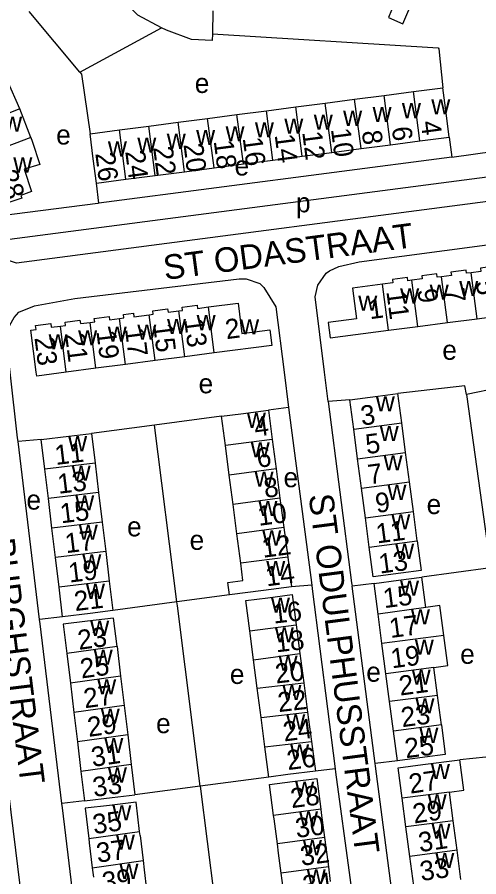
# Model space of a CAD drawing. Extents: x 161141 to 163125, y 381621 to 383200.
# Drawn here: x 162353 to 162447, y 382330.5 to 382505.7 of the extents above; entities that cross this region are included whole.
import ezdxf

# ---------------------------------------------------------------- set-up
doc = ezdxf.new("R2010")
doc.units = 0
for name, color, linetype in [('BLT_Basislijn', 7, 'Continuous'), ('BLT_Bebouwing', 7, 'Continuous'), ('BLT_Centroide', 7, 'Continuous'), ('BLT_Huisnummer', 7, 'Continuous'), ('BLT_Huisnummer_ tussenligend', 7, 'Continuous'), ('BLT_Onderverdeling_panden', 7, 'Continuous'), ('BLT_Straatnaam', 7, 'Continuous')]:
    doc.layers.add(name, color=color, linetype=linetype)

msp = doc.modelspace()

# ---------------------------------------------------------------- linework, layer by layer
at = {"layer": 'BLT_Basislijn'}
for p, q in [((162365.73, 382494.5), (162355.42, 382506.85)), ((162365.73, 382494.5), (162382.4, 382503.53)), ((162440.99, 382481.23), (162441.54, 382477.15)), ((162441.54, 382477.15), (162369.65, 382467.77)), ((162369.65, 382467.77), (162369.15, 382471.85)), ((162457.66, 382431.55), (162444.54, 382428.75)), ((162420.77, 382427.7), (162416.35, 382427.33)), ((162408.28, 382426.15), (162404.17, 382425.59)), ((162408.28, 382426.15), (162412.99, 382389.92)), ((162394.61, 382424.34), (162381, 382422.53)), ((162381, 382422.53), (162368.13, 382420.83)), ((162385.53, 382386.49), (162381, 382422.53)), ((162357.9, 382419.6), (162353.18, 382419.2)), ((162357.58, 382382.92), (162353.18, 382419.2)), ((162449.39, 382393.43), (162435.44, 382391.55)), ((162425.69, 382390.28), (162421.2, 382389.74)), ((162412.99, 382389.92), (162408.89, 382389.59)), ((162425.94, 382353.56), (162421.2, 382389.74)), ((162396.24, 382387.93), (162385.53, 382386.49)), ((162385.53, 382386.49), (162372.48, 382384.73)), ((162362.24, 382383.49), (162357.58, 382382.92)), ((162454.46, 382355.5), (162443.13, 382354.34)), ((162430.43, 382354.13), (162425.94, 382353.56)), ((162417.76, 382352.5), (162413.73, 382352.04)), ((162404.26, 382350.8), (162390.29, 382348.97)), ((162390.29, 382348.97), (162376.98, 382347.21)), ((162390.29, 382348.97), (162395.73, 382305.37)), ((162366.72, 382345.98), (162362.13, 382345.43))]:
    msp.add_line(p, q, dxfattribs=at)
for points in [[(162392.76, 382502.28), (162438.72, 382499.42), (162438.88, 382499.22), (162439.68, 382491.28)], [(162365.73, 382494.5), (162366.1, 382494.08), (162367.84, 382481.91)], [(162441.54, 382477.15), (162459.41, 382479.67), (162461.38, 382480.41), (162463.11, 382482.31), (162463.61, 382484.98)], [(162464.97, 382470.2), (162464.33, 382475.08), (162348.22, 382459.93)], [(162464.97, 382470.2), (162352.84, 382455.52), (162350.45, 382456.39), (162349.43, 382457.35), (162348.52, 382458.94), (162348.22, 382459.93)], [(162369.65, 382467.77), (162369.4, 382467.73), (162346.52, 382464.77)], [(162416.35, 382427.33), (162415.59, 382433.33), (162413.66, 382448.66), (162414.21, 382451.07), (162415.94, 382453.49), (162416.63, 382454), (162418.54, 382454.83), (162422.63, 382455.82), (162466.12, 382461.57)], [(162353.18, 382419.2), (162353.09, 382419.93), (162351.56, 382433.33), (162350.83, 382439.71), (162351.54, 382442.89), (162352.39, 382444.47), (162353.32, 382445.55), (162356.51, 382446.83), (162364.73, 382448.34), (162398.2, 382452.33), (162399.64, 382452.33), (162402.4, 382451.37), (162403.22, 382450.61), (162405.69, 382446.67), (162407.37, 382433.33), (162408.28, 382426.15)], [(162444.54, 382428.75), (162444.2, 382430.57), (162430.54, 382428.98)], [(162416.35, 382427.33), (162421.12, 382390.37), (162421.2, 382389.74)], [(162444.54, 382428.75), (162449.3, 382394.04), (162449.39, 382393.43)], [(162355.54, 382276.25), (162359.22, 382282.82), (162341.87, 382423.88)], [(162412.99, 382389.92), (162413.1, 382389.14), (162417.76, 382352.5)], [(162390.29, 382348.97), (162385.63, 382385.69), (162385.53, 382386.49)], [(162362.13, 382345.43), (162357.68, 382382.05), (162357.58, 382382.92)], [(162431.6, 382310.12), (162431.56, 382310.42), (162426.01, 382353.01), (162425.94, 382353.56)], [(162417.76, 382352.5), (162417.85, 382351.78), (162423.65, 382308.91)], [(162367.4, 382301.68), (162362.24, 382344.51), (162362.13, 382345.43)]]:
    msp.add_lwpolyline(points, dxfattribs=at)
at = {"layer": 'BLT_Bebouwing'}
for p, q in [((162392.85, 382506.99), (162392.76, 382502.28)), ((162353.52, 382486.97), (162351, 382492.7)), ((162427.71, 382489.72), (162433.7, 382490.5)), ((162433.7, 382490.5), (162439.68, 382491.28)), ((162415.74, 382488.16), (162421.72, 382488.94)), ((162421.72, 382488.94), (162427.71, 382489.72)), ((162355.75, 382481.16), (162353.52, 382486.97)), ((162403.76, 382486.6), (162409.75, 382487.38)), ((162409.75, 382487.38), (162415.74, 382488.16)), ((162385.8, 382484.25), (162391.79, 382485.03)), ((162391.79, 382485.03), (162397.77, 382485.81)), ((162397.77, 382485.81), (162403.76, 382486.6)), ((162373.83, 382482.69), (162379.81, 382483.47)), ((162379.81, 382483.47), (162385.8, 382484.25)), ((162367.84, 382481.91), (162373.83, 382482.69)), ((162423.04, 382478.88), (162429.02, 382479.66)), ((162429.02, 382479.66), (162435.01, 382480.45)), ((162435.01, 382480.45), (162440.99, 382481.23)), ((162411.06, 382477.32), (162417.05, 382478.1)), ((162417.05, 382478.1), (162423.04, 382478.88)), ((162399.09, 382475.76), (162405.07, 382476.54)), ((162405.07, 382476.54), (162411.06, 382477.32)), ((162387.11, 382474.19), (162393.1, 382474.98)), ((162393.1, 382474.98), (162399.09, 382475.76)), ((162369.15, 382471.85), (162375.14, 382472.63)), ((162375.14, 382472.63), (162381.13, 382473.41)), ((162381.13, 382473.41), (162387.11, 382474.19)), ((162446.65, 382444.22), (162452.66, 382445)), ((162434.63, 382442.65), (162440.64, 382443.43)), ((162440.64, 382443.43), (162446.65, 382444.22)), ((162428.62, 382441.86), (162434.63, 382442.65)), ((162387.12, 382436.48), (162381.09, 382435.69)), ((162393.15, 382437.26), (162387.12, 382436.48)), ((162369.04, 382434.11), (162363.01, 382433.32)), ((162375.07, 382434.9), (162369.04, 382434.11)), ((162381.09, 382435.69), (162375.07, 382434.9)), ((162431.33, 382422.97), (162430.54, 382428.98)), ((162421.55, 382421.69), (162420.77, 382427.7)), ((162404.17, 382425.59), (162404.96, 382419.61)), ((162395.4, 382418.35), (162394.61, 382424.34)), ((162432.12, 382416.96), (162431.33, 382422.97)), ((162368.13, 382420.83), (162368.86, 382414.81)), ((162422.34, 382415.68), (162421.55, 382421.69)), ((162358.62, 382413.58), (162357.9, 382419.6)), ((162396.18, 382412.36), (162395.4, 382418.35)), ((162404.96, 382419.61), (162405.74, 382413.62)), ((162432.9, 382410.95), (162432.12, 382416.96)), ((162368.86, 382414.81), (162369.58, 382408.79)), ((162423.13, 382409.67), (162422.34, 382415.68)), ((162359.35, 382407.56), (162358.62, 382413.58)), ((162405.74, 382413.62), (162406.52, 382407.63)), ((162396.96, 382406.37), (162396.18, 382412.36)), ((162423.91, 382403.66), (162423.13, 382409.67)), ((162433.69, 382404.94), (162432.9, 382410.95)), ((162369.58, 382408.79), (162370.31, 382402.78)), ((162360.07, 382401.54), (162359.35, 382407.56)), ((162397.75, 382400.38), (162396.96, 382406.37)), ((162406.52, 382407.63), (162407.31, 382401.64)), ((162434.48, 382398.93), (162433.69, 382404.94)), ((162370.31, 382402.78), (162371.03, 382396.76)), ((162424.7, 382397.66), (162423.91, 382403.66)), ((162360.8, 382395.53), (162360.07, 382401.54)), ((162407.31, 382401.64), (162408.09, 382395.65)), ((162398.53, 382394.38), (162397.75, 382400.38)), ((162361.52, 382389.51), (162360.8, 382395.53)), ((162371.03, 382396.76), (162371.76, 382390.74)), ((162408.09, 382395.65), (162408.89, 382389.59)), ((162371.76, 382390.74), (162372.48, 382384.73)), ((162426.52, 382383.99), (162425.69, 382390.28)), ((162436.25, 382385.4), (162435.44, 382391.55)), ((162362.24, 382383.49), (162361.52, 382389.51)), ((162427.3, 382378.01), (162426.52, 382383.99)), ((162409.83, 382381.85), (162410.6, 382375.97)), ((162401.13, 382374.73), (162400.36, 382380.6)), ((162428.11, 382371.85), (162427.3, 382378.01)), ((162373.34, 382377.4), (162374.07, 382371.4)), ((162363.11, 382375.97), (162363.83, 382369.97)), ((162401.89, 382368.95), (162401.13, 382374.73)), ((162410.6, 382375.97), (162411.37, 382370.02)), ((162438.6, 382367.46), (162437.86, 382373.14)), ((162374.07, 382371.4), (162374.79, 382365.4)), ((162428.85, 382366.18), (162428.11, 382371.85)), ((162363.83, 382369.97), (162364.55, 382363.97)), ((162411.37, 382370.02), (162412.16, 382364.03)), ((162402.67, 382362.96), (162401.89, 382368.95)), ((162429.64, 382360.16), (162428.85, 382366.18)), ((162439.39, 382361.43), (162438.6, 382367.46)), ((162374.79, 382365.4), (162375.51, 382359.4)), ((162412.16, 382364.03), (162412.94, 382358.03)), ((162364.55, 382363.97), (162365.28, 382357.97)), ((162403.45, 382356.96), (162402.67, 382362.96)), ((162375.51, 382359.4), (162376.23, 382353.4)), ((162430.43, 382354.13), (162429.64, 382360.16)), ((162365.28, 382357.97), (162366, 382351.97)), ((162412.94, 382358.03), (162413.73, 382352.04)), ((162404.26, 382350.8), (162403.45, 382356.96)), ((162366, 382351.97), (162366.72, 382345.98)), ((162376.23, 382353.4), (162376.98, 382347.21)), ((162432.17, 382340.67), (162431.41, 382346.49)), ((162441.8, 382341.87), (162441.03, 382347.76)), ((162405.32, 382342.28), (162405.23, 382343.01)), ((162414.84, 382344.28), (162414.94, 382343.54)), ((162414.94, 382343.54), (162415.6, 382338.47)), ((162405.99, 382337.21), (162405.32, 382342.28)), ((162442.58, 382335.9), (162441.8, 382341.87)), ((162378.03, 382338.89), (162377.93, 382339.74)), ((162432.96, 382334.65), (162432.17, 382340.67)), ((162367.58, 382338.29), (162367.68, 382337.44)), ((162378.03, 382338.89), (162378.64, 382333.78)), ((162415.6, 382338.47), (162415.85, 382336.53)), ((162367.68, 382337.44), (162368.3, 382332.33)), ((162406.24, 382335.27), (162405.99, 382337.21)), ((162415.85, 382336.53), (162416.38, 382332.51)), ((162406.77, 382331.25), (162406.24, 382335.27)), ((162433.75, 382328.64), (162432.96, 382334.65)), ((162443.37, 382329.93), (162442.58, 382335.9)), ((162378.64, 382333.78), (162378.87, 382331.88)), ((162416.38, 382332.51), (162416.77, 382329.52)), ((162368.3, 382332.33), (162368.52, 382330.44)), ((162378.87, 382331.88), (162379.36, 382327.82)), ((162407.16, 382328.26), (162406.77, 382331.25))]:
    msp.add_line(p, q, dxfattribs=at)
for points in [[(162431.53, 382504.34), (162435.06, 382512.6), (162437.03, 382517.19), (162434.9, 382518.1), (162435.17, 382518.74), (162431.98, 382520.11), (162431.71, 382519.46), (162430.98, 382519.78)], [(162382.4, 382503.53), (162377.58, 382506.11), (162371.77, 382512.16), (162376.64, 382515.63)], [(162426.76, 382509.91), (162429.88, 382508.58), (162428.6, 382505.6), (162431.53, 382504.34)], [(162392.76, 382502.28), (162392.73, 382500.94), (162388.51, 382501.12), (162383.4, 382503), (162382.4, 382503.53)], [(162440.99, 382481.23), (162440.34, 382486.18), (162439.68, 382491.28)], [(162369.15, 382471.85), (162368.51, 382476.81), (162367.84, 382481.91)], [(162355.75, 382481.16), (162356.04, 382480.42), (162357.63, 382475.68), (162354.43, 382474.71), (162355.93, 382470.18), (162353.73, 382469.36), (162353.95, 382468.78), (162351.08, 382467.85), (162350.85, 382468.46), (162349.99, 382468.17), (162346.82, 382477.73)], [(162439.42, 382452.79), (162438.56, 382452.68), (162438.47, 382453.39), (162435.42, 382452.99), (162435.51, 382452.34), (162433.4, 382452.06)], [(162445.43, 382453.59), (162444.53, 382453.48), (162444.45, 382454.09), (162441.34, 382453.69), (162441.43, 382453.05), (162439.42, 382452.79)], [(162451.44, 382454.38), (162450.4, 382454.24), (162450.31, 382454.91), (162447.37, 382454.52), (162447.46, 382453.86), (162445.43, 382453.59)], [(162433.4, 382452.06), (162432.59, 382451.96), (162432.5, 382452.62), (162429.41, 382452.22), (162429.5, 382451.53), (162427.39, 382451.25)], [(162427.39, 382451.25), (162421.32, 382450.46), (162422.13, 382444.21), (162416.31, 382443.45), (162416.72, 382440.31), (162428.62, 382441.86)], [(162385.93, 382445.84), (162386.68, 382445.93), (162386.59, 382446.6), (162389.64, 382447), (162389.73, 382446.32), (162391.96, 382446.61)], [(162391.96, 382446.61), (162397.98, 382447.4), (162398.78, 382441.22), (162404.44, 382441.96), (162404.85, 382438.79), (162393.15, 382437.26)], [(162367.85, 382443.48), (162368.8, 382443.6), (162368.71, 382444.29), (162371.73, 382444.68), (162371.81, 382444.01), (162373.87, 382444.28)], [(162373.87, 382444.28), (162374.73, 382444.39), (162374.64, 382445.1), (162376.66, 382445.36), (162376.76, 382444.6), (162379.91, 382445.02)], [(162379.91, 382445.02), (162380.72, 382445.12), (162380.63, 382445.85), (162383.64, 382446.24), (162383.73, 382445.55), (162385.93, 382445.84)], [(162363.01, 382433.32), (162356.98, 382432.54), (162356.88, 382433.33), (162355.76, 382441.89), (162356.86, 382442.04), (162356.76, 382442.81), (162359.85, 382443.22), (162359.94, 382442.48), (162361.82, 382442.72)], [(162361.82, 382442.72), (162362.84, 382442.86), (162362.75, 382443.55), (162365.78, 382443.94), (162365.88, 382443.22), (162367.85, 382443.48)], [(162420.77, 382427.7), (162426.43, 382428.44), (162430.54, 382428.98)], [(162394.61, 382424.34), (162398.55, 382424.85), (162404.17, 382425.59)], [(162357.9, 382419.6), (162363.53, 382420.27), (162368.13, 382420.83)], [(162434.48, 382398.93), (162435.26, 382392.93), (162431.11, 382392.38), (162425.49, 382391.65), (162424.7, 382397.66)], [(162396.24, 382387.93), (162395.91, 382390.43), (162398.99, 382390.84), (162398.53, 382394.38)], [(162425.69, 382390.28), (162430.64, 382390.93), (162435.44, 382391.55)], [(162408.89, 382389.59), (162403.2, 382388.85), (162396.24, 382387.93)], [(162400.36, 382380.6), (162399.56, 382386.77), (162404.07, 382387.36), (162409.02, 382388.01), (162409.83, 382381.85)], [(162439.88, 382379.68), (162439.08, 382385.77), (162436.25, 382385.4)], [(162372.48, 382384.73), (162367.87, 382384.17), (162362.24, 382383.49)], [(162373.34, 382377.4), (162372.64, 382383.21), (162367.35, 382382.57), (162362.38, 382381.97), (162363.11, 382375.97)], [(162437.86, 382373.14), (162440.68, 382373.52), (162439.88, 382379.68)], [(162439.39, 382361.43), (162440.18, 382355.41), (162436.05, 382354.87), (162430.43, 382354.13)], [(162431.41, 382346.49), (162430.6, 382352.7), (162435.59, 382353.35), (162443.13, 382354.34)], [(162441.03, 382347.76), (162443.94, 382348.14), (162443.13, 382354.34)], [(162413.73, 382352.04), (162408.13, 382351.31), (162404.26, 382350.8)], [(162405.23, 382343.01), (162404.41, 382349.29), (162409.06, 382349.9), (162414.02, 382350.55), (162414.84, 382344.28)], [(162366.72, 382345.98), (162372.35, 382346.66), (162376.98, 382347.21)], [(162377.93, 382339.74), (162377.21, 382345.7), (162371.8, 382345.05), (162366.84, 382344.45), (162367.58, 382338.29)]]:
    msp.add_lwpolyline(points, dxfattribs=at)
at = {"layer": 'BLT_Onderverdeling_panden'}
for p, q in [((162435.01, 382480.45), (162433.7, 382490.5)), ((162423.04, 382478.88), (162421.72, 382488.94)), ((162429.02, 382479.66), (162427.71, 382489.72)), ((162353.52, 382486.97), (162344.53, 382483.52)), ((162411.06, 382477.32), (162409.75, 382487.38)), ((162417.05, 382478.1), (162415.74, 382488.16)), ((162393.1, 382474.98), (162391.79, 382485.03)), ((162399.09, 382475.76), (162397.77, 382485.81)), ((162405.07, 382476.54), (162403.76, 382486.6)), ((162381.13, 382473.41), (162379.81, 382483.47)), ((162387.11, 382474.19), (162385.8, 382484.25)), ((162375.14, 382472.63), (162373.83, 382482.69)), ((162355.75, 382481.16), (162346.82, 382477.73)), ((162446.65, 382444.22), (162445.43, 382453.59)), ((162434.63, 382442.65), (162433.4, 382452.06)), ((162440.64, 382443.43), (162439.42, 382452.79)), ((162428.62, 382441.86), (162427.39, 382451.25)), ((162393.15, 382437.26), (162391.96, 382446.61)), ((162381.09, 382435.69), (162379.91, 382445.02)), ((162387.12, 382436.48), (162385.93, 382445.84)), ((162369.04, 382434.11), (162367.85, 382443.48)), ((162375.07, 382434.9), (162373.87, 382444.28)), ((162363.01, 382433.32), (162361.82, 382442.72)), ((162421.55, 382421.69), (162431.33, 382422.97)), ((162404.96, 382419.61), (162395.4, 382418.35)), ((162422.34, 382415.68), (162432.12, 382416.96)), ((162368.86, 382414.81), (162358.62, 382413.58)), ((162405.74, 382413.62), (162396.18, 382412.36)), ((162423.13, 382409.67), (162432.9, 382410.95)), ((162369.58, 382408.79), (162359.35, 382407.56)), ((162406.52, 382407.63), (162396.96, 382406.37)), ((162423.91, 382403.66), (162433.69, 382404.94)), ((162370.31, 382402.78), (162360.07, 382401.54)), ((162407.31, 382401.64), (162397.75, 382400.38)), ((162424.7, 382397.66), (162434.48, 382398.93)), ((162371.03, 382396.76), (162360.8, 382395.53)), ((162408.09, 382395.65), (162398.53, 382394.38)), ((162371.76, 382390.74), (162361.52, 382389.51)), ((162436.25, 382385.4), (162426.52, 382383.99)), ((162400.36, 382380.6), (162409.83, 382381.85)), ((162439.88, 382379.68), (162427.3, 382378.01)), ((162373.34, 382377.4), (162363.11, 382375.97)), ((162401.13, 382374.73), (162410.6, 382375.97)), ((162437.86, 382373.14), (162428.11, 382371.85)), ((162374.07, 382371.4), (162363.83, 382369.97)), ((162401.89, 382368.95), (162411.37, 382370.02)), ((162438.6, 382367.46), (162428.85, 382366.18)), ((162374.79, 382365.4), (162364.55, 382363.97)), ((162402.67, 382362.96), (162412.16, 382364.03)), ((162439.39, 382361.43), (162429.64, 382360.16)), ((162375.51, 382359.4), (162365.28, 382357.97)), ((162403.45, 382356.96), (162412.94, 382358.03)), ((162376.23, 382353.4), (162366, 382351.97)), ((162441.03, 382347.76), (162431.41, 382346.49)), ((162414.84, 382344.28), (162405.23, 382343.01)), ((162441.8, 382341.87), (162432.17, 382340.67)), ((162367.58, 382338.29), (162377.93, 382339.74)), ((162415.6, 382338.47), (162405.99, 382337.21)), ((162442.58, 382335.9), (162432.96, 382334.65)), ((162368.3, 382332.33), (162378.64, 382333.78)), ((162416.38, 382332.51), (162406.77, 382331.25))]:
    msp.add_line(p, q, dxfattribs=at)

# ---------------------------------------------------------------- texts
at = {"layer": 'BLT_Centroide'}
for s, p in [('e', (162389.17, 382490.23)), ('w', (162437.34, 382485.86)), ('w', (162425.38, 382484.3)), ('w', (162431.36, 382485.08)), ('w', (162350.15, 382482.34)), ('w', (162407.41, 382481.95)), ('w', (162413.41, 382482.73)), ('w', (162419.39, 382483.52)), ('w', (162395.44, 382480.39)), ('w', (162401.42, 382481.17)), ('e', (162360.94, 382479.72)), ('w', (162383.47, 382478.83)), ('w', (162389.45, 382479.61)), ('w', (162371.48, 382477.27)), ('w', (162377.47, 382478.05)), ('w', (162352.22, 382474.02)), ('e', (162397.28, 382473.41)), ('p', (162409.78, 382465.9)), ('w', (162443.03, 382448.83)), ('w', (162431, 382447.31)), ('w', (162437.02, 382448.08)), ('w', (162422.47, 382445.83)), ('w', (162389.55, 382441.88)), ('w', (162377.48, 382439.95)), ('w', (162383.52, 382441.11)), ('w', (162398.41, 382441.02)), ('w', (162359.39, 382438)), ('w', (162365.42, 382438.77)), ('w', (162371.45, 382439.55)), ('e', (162439.58, 382435.85)), ('e', (162389.95, 382429.02)), ('w', (162426.05, 382425.34)), ('w', (162399.78, 382421.97)), ('w', (162426.84, 382419.31)), ('w', (162363.38, 382417.22)), ('w', (162400.57, 382415.97)), ('w', (162427.62, 382413.31)), ('w', (162364.1, 382411.19)), ('w', (162401.35, 382410)), ('e', (162407.25, 382409.88)), ('w', (162428.41, 382407.31)), ('e', (162354.89, 382405.32)), ('w', (162364.83, 382405.16)), ('w', (162402.13, 382404)), ('e', (162436.39, 382404.41)), ('w', (162429.2, 382401.31)), ('e', (162375.38, 382399.86)), ('w', (162365.55, 382399.16)), ('w', (162402.92, 382398)), ('e', (162388.12, 382397.12)), ('w', (162429.98, 382395.28)), ('w', (162366.27, 382393.12)), ('w', (162403.73, 382391.78)), ('w', (162430.98, 382387.78)), ('w', (162367, 382387.12)), ('w', (162404.69, 382384.31)), ('w', (162433.2, 382381.91)), ('w', (162367.88, 382379.59)), ('w', (162405.48, 382378.28)), ('w', (162433.99, 382375.75)), ('w', (162368.59, 382373.69)), ('e', (162443.22, 382373.89)), ('w', (162406.24, 382372.47)), ('e', (162396.32, 382369.79)), ('e', (162424.1, 382370.24)), ('w', (162433.35, 382369.66)), ('w', (162369.31, 382367.69)), ('w', (162407.02, 382366.5)), ('w', (162434.12, 382363.81)), ('w', (162370.03, 382361.69)), ('e', (162381.29, 382359.76)), ('w', (162407.8, 382360.5)), ('w', (162434.91, 382357.78)), ('w', (162370.75, 382355.69)), ('w', (162408.6, 382354.41)), ('w', (162437.27, 382350.41)), ('w', (162371.48, 382349.69)), ('w', (162409.62, 382346.78)), ('w', (162436.6, 382344.22)), ('w', (162372.39, 382342)), ('w', (162410.41, 382340.75)), ('w', (162437.38, 382338.25)), ('w', (162373.11, 382336.03)), ('w', (162411.19, 382334.88)), ('w', (162438.16, 382332.28)), ('w', (162373.83, 382330.06)), ('w', (162411.97, 382328.91))]:
    msp.add_text(s, height=4, dxfattribs=at).set_placement(p)
at = {"layer": 'BLT_Huisnummer'}
for s, rotation, p in [('4', 277.4363, (162435.18, 382484.35)), ('12', 277.4348, (162411.04, 382482.23)), ('8', 277.4355, (162423.18, 382482.4)), ('20', 277.439, (162386.86, 382479.74)), ('16', 277.4397, (162398.92, 382481.02)), ('26', 277.4349, (162368.9, 382477.91)), ('24', 277.4382, (162375, 382478.3)), ('28', 288.2934, (162349.01, 382473.83)), ('5', 277.4526, (162446.4, 382451.77)), ('9', 277.4496, (162434.48, 382450.14)), ('1', 7.439, (162424.84, 382444.11)), ('11', 277.452, (162428.18, 382449.78)), ('13', 277.2427, (162387, 382444.08)), ('2', 7.4494, (162395.63, 382440.04)), ('17', 277.2422, (162374.94, 382442.18)), ('23', 277.4486, (162356.51, 382440.35)), ('3', 7.4602, (162423.19, 382422.44)), ('4', 7.531, (162401.51, 382420.15)), ('11', 6.8589, (162360.88, 382414.41)), ('7', 7.4652, (162424.66, 382410.45)), ('8', 7.5303, (162403.49, 382407.68)), ('15', 6.8637, (162361.96, 382402.51)), ('11', 7.458, (162426.31, 382398.41)), ('12', 7.5287, (162403.08, 382395.49)), ('19', 6.8569, (162363.65, 382390.44)), ('15', 7.4595, (162427.77, 382385.22)), ('16', 6.4277, (162405.25, 382382.08)), ('23', 7.9302, (162365.59, 382376.72)), ('19', 7.4653, (162429.33, 382372.96)), ('20', 6.4283, (162405.74, 382369.87)), ('27', 7.9372, (162366.8, 382364.82)), ('23', 7.4661, (162431.42, 382360.97)), ('24', 7.4585, (162407.39, 382358.05)), ('31', 7.9325, (162368.35, 382352.88)), ('27', 8.3965, (162433.07, 382347.41)), ('28', 7.4556, (162408.9, 382344.47)), ('35', 7.9556, (162368.65, 382339.17)), ('31', 8.3898, (162435, 382335.49)), ('32', 7.4548, (162410.9, 382332.72)), ('39', 7.9556, (162370.59, 382327.4))]:
    msp.add_text(s, height=4, rotation=rotation, dxfattribs=at).set_placement(p)
at = {"layer": 'BLT_Huisnummer_ tussenligend'}
for s, rotation, p in [('6', 277.4363, (162429.28, 382483.17)), ('14', 277.4348, (162405.43, 382481.66)), ('10', 277.4355, (162416.89, 382482.86)), ('18', 277.4397, (162393.02, 382480.42)), ('22', 277.439, (162380.67, 382479.14)), ('7', 277.4526, (162440.07, 382450.26)), ('15', 277.2427, (162380.67, 382443.07)), ('21', 277.2414, (162362.73, 382441.1)), ('19', 277.2422, (162369.12, 382441.66)), ('5', 7.4602, (162424.2, 382416.62)), ('6', 7.531, (162402.02, 382413.82)), ('13', 6.8589, (162361.44, 382408.53)), ('9', 7.4652, (162426.19, 382404.62)), ('10', 7.5303, (162402.23, 382402)), ('17', 6.8637, (162362.96, 382396.43)), ('13', 7.458, (162426.88, 382392.27)), ('14', 7.5287, (162403.82, 382389.66)), ('21', 6.8569, (162364.83, 382384.63)), ('17', 7.4595, (162429.02, 382379.14)), ('18', 6.4277, (162405.76, 382376.22)), ('25', 7.9302, (162366.09, 382370.89)), ('21', 7.4653, (162431.01, 382367.41)), ('22', 6.4283, (162406.26, 382364.04)), ('29', 7.9372, (162367.57, 382358.99)), ('25', 7.4661, (162432.18, 382354.64)), ('26', 7.4585, (162408.15, 382352.22)), ('33', 7.9325, (162368.66, 382346.74)), ('29', 8.3965, (162433.84, 382341.33)), ('30', 7.4556, (162409.9, 382338.39)), ('37', 7.9556, (162369.4, 382333.34)), ('33', 8.3898, (162435.31, 382329.6)), ('34', 7.4548, (162411.4, 382326.71))]:
    msp.add_text(s, height=4, rotation=rotation, dxfattribs=at).set_placement(p)
at = {"layer": 'BLT_Straatnaam'}
for s, height, rotation, p in [('ST ODASTRAAT', 5, 7.5108, (162383.1, 382452.11)), ('ST ODULPHUSSTRAAT', 5, 277.4112, (162412.34, 382408.25)), ('BURGHSTRAAT', 4.9999, 277.1082, (162347.46, 382399.25))]:
    msp.add_text(s, height=height, rotation=rotation, dxfattribs=at).set_placement(p)

doc.saveas('drawing.dxf')
